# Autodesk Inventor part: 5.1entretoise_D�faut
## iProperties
Created: 2011-01
Part Number: 5.1entretoise_D�faut
Document SubType Name: Modeling
Designer: eric
Density: 1 g/cm^3
Mass: 0.706858 g
Surface Area: 14.7027 cm^2
Volume: 0.706858 cm^3
Author: eric
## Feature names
1. Base1
